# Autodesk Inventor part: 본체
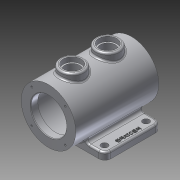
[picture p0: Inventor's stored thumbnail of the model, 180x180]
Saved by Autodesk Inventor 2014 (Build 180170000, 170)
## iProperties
Created: 2014-12
Part Number: 본체
Material: 알루미늄 6061
Document SubType Name: Modeling
Designer: Owner
Density: 2.71 g/cm^3
Appearance: 알루미늄 - 평지
Mass: 1294.2 g
Surface Area: 1040.72 cm^2
Volume: 477.565 cm^3
Author: Owner
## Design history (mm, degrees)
sketch "스케치3"
  geometry: C1 r 46 at (0, 0); 1 further point
  constraints: 1 centre point, 1 coincident
  dimensions: "d0" = 92 diameter of C1
extrude "돌출1" new body sketch "스케치3" stored distance "d1" = 140; taper "d2" = 0 deg
hole "구멍1" diameter "d5" = 60; stored, may be unused: countersink angle "d9" = 90 deg, drill point angle "d11" = 0 deg; dims "d3" = 10, "d4" = 10, "d6" = 6, "d7" = 4, "d8" = 2, "d10" = 12
hole "구멍2" diameter "d14" = 60; stored, may be unused: countersink angle "d18" = 90 deg, drill point angle "d20" = 0 deg; dims "d12" = 10, "d13" = 10, "d15" = 6, "d16" = 4, "d17" = 2, "d19" = 12
sketch "스케치5"
  geometry: C1 r 30 at (0, 0) reference; C2 r 37.5 at (0, 0)
  constraints: 1 centre point, 1 coincident
  dimensions: "d21" = 75 diameter of C2
extrude "돌출2" cut sketch "스케치5" distance "d22" = 116; taper "d23" = 0 deg
node "작업 평면1"
sketch "스케치6"
  geometry: L1 (-46, -70)-(46, -70) reference; C1 r 20 at (0, -30); C2 r 20 at (0, 30); 1 further point
  constraints: 2 centre point, 2 vertical alignment
  dimensions: "d25" = 40 diameter of C1; "d26" = 40 diameter of C2; "d27" = 60 distance of C2.centre C1.centre; "d28" = 40 distance from line of C1.centre L1
extrude "돌출3" join sketch "스케치6" stored distance "d29" = 116; taper "d30" = 0 deg
hole "구멍3" diameter "d33" = 25; stored, may be unused: countersink angle "d37" = 90 deg, drill point angle "d39" = 0 deg; dims "d31" = 10, "d32" = 10, "d34" = 6, "d35" = 30, "d36" = 8, "d38" = 12
hole "구멍4" diameter "d42" = 25; stored, may be unused: countersink angle "d46" = 90 deg, drill point angle "d48" = 0 deg; dims "d40" = 10, "d41" = 10, "d43" = 6, "d44" = 30, "d45" = 8, "d47" = 12
node "작업 평면2"
sketch "스케치7"
  geometry: L1 (-65, -40)-(65, -40); L2 (65, -40)-(65, 55); L3 (65, 55)-(-65, 55); L4 (-65, 55)-(-65, -40); L5 (46, 70)-(-46, 70) reference; 2 further points
  constraints: 8 end point, 2 parallel, 1 horizontal, 1 midpoint, 1 perpendicular, 1 vertical alignment
  dimensions: "d50" = 95 distance of L3.end L1.start; "d51" = 15 distance between parallel lines of L5 L3; "d52" = 130 distance between parallel lines of L2 L4
extrude "돌출4" join sketch "스케치7" distance "d53" = 12; taper "d54" = 0 deg
sketch "스케치9"
  geometry: L1 (65, 55)-(25.923, 55) reference; C1 r 5.5 at (52, -27.5); C2 r 5.5 at (52, 42.5); 1 further point
  constraints: 2 centre point, 1 equal radius
  dimensions: "d55" = 11 diameter of C1; "d56" = 12.5 distance from line of C2.centre L1; "d57" = 70 distance of C1.centre C2.centre; "d58" = 52 horizontal distance of point (0, 0) C2.centre; "d59" = 52 horizontal distance of C1.centre point (0, 0)
extrude "돌출5" cut sketch "스케치9" stored distance "d60" = 12; taper "d61" = 0 deg
sketch "스케치10"
  geometry: L1 (65, -40)-(65, 55) reference; C1 r 5.5 at (52, -27.5) reference; 2 further points
  constraints: 1 other
  dimensions: "d62" = 35 vertical distance of C1.centre point (57, 7.5); "d63" = 8 distance from line of point (57, 7.5) L1
feature "엠보싱1" sketch "스케치10" dims "d64" = 1, "d65" = 0
fillet "모깎기1" dims "d66" = 10
fillet "모깎기2" dims "d67" = 5
fillet "모깎기3" dims "d68" = 3
fillet "모깎기4" dims "d69" = 1
sketch "스케치11"
  geometry: L1 (0, 0)-(28.284, 28.284); L2 (0, 0)-(40, 0); C1 r 31 at (0, 0) reference; 1 further point
  constraints: 4 end point, 1 coincident, 1 equal length, 1 horizontal
  dimensions: "d70" = 40 distance of L1.start L1.end; "d71" = 45 deg angle of L2 L1
hole "구멍5" sketch "스케치11" at (28.284, 28.284) diameter "d72" = 3.242; stored, may be unused: countersink angle "d76" = 90 deg, drill point angle "d78" = 118 deg; dims "d73" = 8, "d74" = 30, "d75" = 8, "d77" = 10
node "솔리드1"
mirror "대칭1"
pattern_circular "원형 패턴1" dims angle "d80" = 360 deg
mirror "대칭2"
other parameters: "d24" = 56
